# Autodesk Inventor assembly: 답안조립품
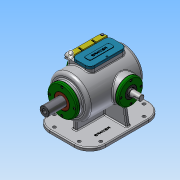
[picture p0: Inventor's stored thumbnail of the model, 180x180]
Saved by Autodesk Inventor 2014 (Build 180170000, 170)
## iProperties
Created: 2019-10
Part Number: 답안조립품
Document SubType Name: Assembly
Designer: net
Mass: 7796.24 g
Surface Area: 4928.11 cm^2
Volume: 2172.89 cm^3
Density: 3.58795 g/cm^3
Author: net
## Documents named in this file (17)
- C:\Users\net\Desktop\391004V1029\답안조립품.iam
- C:\Users\net\Desktop\391004V1029\본체.ipt
- C:\Users\net\Desktop\391004V1029\개스킷 A.ipt
- C:\Users\net\Desktop\391004V1029\개스킷 B.ipt
- C:\Users\net\Desktop\391004V1029\베어링 6205.ipt
- 베어링 6205.ipt
- C:\Users\net\Desktop\391004V1029\축 커버.ipt
- C:\Users\net\Desktop\391004V1029\오일 실 25 38 8.ipt
- C:\Users\net\Desktop\391004V1029\슬라이드 커버.ipt
- C:\Users\net\Desktop\391004V1029\부시.ipt
- C:\Users\net\Desktop\391004V1029\슬라이드.ipt
- C:\Users\net\Desktop\391004V1029\편심축.ipt
- C:\Users\net\Desktop\391004V1029\볼트 M4x0.7.ipt
- C:\Users\net\Desktop\391004V1029\상부커버.ipt
- C:\Users\net\Desktop\391004V1029\고정플레이트.ipt
- C:\Users\net\Desktop\391004V1029\육각머리볼트 M4.ipt
- C:\Users\net\Desktop\391004V1029\가변스프링.ipt
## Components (17 placed, 5 different names)
1. 개스킷 A:1
2. 개스킷 B:1
3. 개스킷 B:2
4. 고정플레이트:1 — 플러쉬:1
5. 가변스프링:1
6. M4x0.7:3
7. M4x0.7:4
8. M4x0.7:5
9. M4x0.7:6
10. M4x0.7:1
11. M4x0.7:7
12. M4x0.7:8
13. M4x0.7:9
14. M4x0.7:2
15. M4x0.7:10
16. M4x0.7:11
17. M4x0.7:12
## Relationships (1: Flush 1)
- 플러쉬:1 [Flush]: 고정플레이트:1
